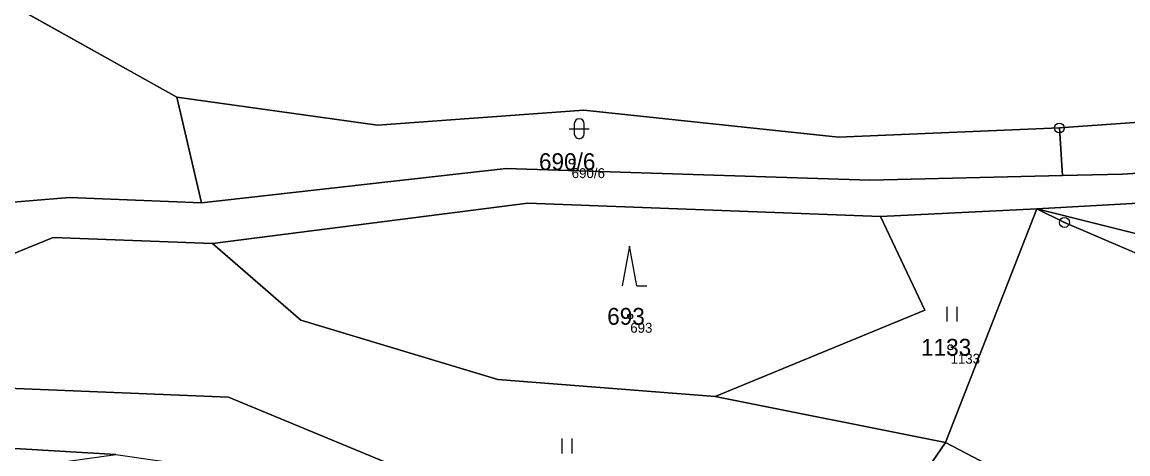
# Model space of a CAD drawing. Extents: x -554500 to -548272, y -1079733 to -1073730.
# Drawn here: x -553201.1 to -553089.7, y -1076736.6 to -1076693.1 of the extents above; entities that cross this region are included whole.
import ezdxf

# ---------------------------------------------------------------- set-up
doc = ezdxf.new("R2010")
doc.units = 0
for name, color, linetype in [('Definiční body', 7, 'Continuous'), ('Hranice parcel', 7, 'Continuous'), ('Parcelní čísla', 7, 'Continuous'), ('Polygon parcely', 7, 'Continuous'), ('Značky bodu BP', 7, 'Continuous'), ('Značky kultur', 7, 'Continuous')]:
    doc.layers.add(name, color=color, linetype=linetype)

msp = doc.modelspace()

# ---------------------------------------------------------------- linework, layer by layer
at = {"layer": 'Definiční body'}
for centre in [(-553145.73, -1076707.13994), (-553139.83, -1076722.73994), (-553107.55, -1076725.85994)]:
    msp.add_circle(centre, 0.25, dxfattribs=at)
at = {"layer": 'Hranice parcel'}
for p, q in [((-553185.54, -1076700.62), (-553217.33, -1076682.85)), ((-553183.05, -1076711.3), (-553185.54, -1076700.62)), ((-553096.58, -1076703.74), (-553096.28, -1076708.55)), ((-553098.85, -1076711.9), (-553114.62, -1076712.68)), ((-553098.85, -1076711.9), (-553108.07, -1076735.46)), ((-553108.07, -1076735.46), (-553131.27, -1076730.84))]:
    msp.add_line(p, q, dxfattribs=at)
for points in [[(-553098.85, -1076711.9), (-552980.39, -1076705.28), (-552939.43, -1076698.63), (-552921.85, -1076693.28), (-552862.63, -1076685.38), (-552777.87, -1076661.95), (-552759.32, -1076653.97), (-552709.11, -1076612.75)], [(-553040.22, -1076662.97), (-553036.57, -1076699.47), (-553096.58, -1076703.74)], [(-553096.28, -1076708.55), (-553090.21, -1076708.4), (-553016.61, -1076703.6), (-552983.69, -1076702.31), (-552965.52, -1076700.06), (-552940.21, -1076695.7), (-552920.53, -1076689.68)], [(-553185.54, -1076700.62), (-553165.31, -1076703.44), (-553144.52, -1076701.93), (-553118.83, -1076704.66), (-553096.58, -1076703.74)], [(-553183.05, -1076711.3), (-553152.34, -1076707.84), (-553115.69, -1076709.01), (-553096.28, -1076708.55)], [(-552942.15, -1076708.95), (-552975.92, -1076713.65), (-552999.87, -1076711.28), (-553084.6, -1076715.45), (-553098.85, -1076711.9)], [(-553230.16, -1076713.55), (-553196.34, -1076710.75), (-553183.05, -1076711.3)], [(-553114.62, -1076712.68), (-553150.14, -1076711.34), (-553181.93, -1076715.39)], [(-553131.27, -1076730.84), (-553110.15, -1076722.11), (-553114.62, -1076712.68)], [(-553098.85, -1076711.9), (-553096.07, -1076713.27), (-553012.42, -1076749.19), (-552945.41, -1076753.61)], [(-553181.93, -1076715.39), (-553198, -1076714.8), (-553232.31, -1076728.79)], [(-553181.93, -1076715.39), (-553173.02, -1076723.12), (-553153.18, -1076729.11), (-553131.27, -1076730.84)], [(-553091.12, -1076778.22), (-553119.71, -1076763.47), (-553143.59, -1076748.76), (-553160.35, -1076739.17), (-553180.32, -1076730.88), (-553232.31, -1076728.79)], [(-553191.68, -1076736.66), (-553222.8, -1076734.83), (-553250.13, -1076734.54)], [(-553108.07, -1076735.46), (-553121.9, -1076755.7), (-553091.12, -1076778.22)], [(-553108.07, -1076735.46), (-553058.34, -1076761.55), (-553042.36, -1076760.43)]]:
    msp.add_lwpolyline(points, dxfattribs=at)
at = {"layer": 'Polygon parcely'}
for points in [[(-552883.03, -1076530.17), (-552893.61, -1076543.86), (-552911.35, -1076561.18), (-552940.69, -1076584.39), (-552992.07, -1076615.06), (-553008.87, -1076623.57), (-553058.19, -1076636.88), (-553040.22, -1076662.97), (-553036.57, -1076699.47), (-553096.58, -1076703.74), (-553096.28, -1076708.55), (-553090.21, -1076708.4), (-553016.61, -1076703.6), (-552983.69, -1076702.31), (-552965.52, -1076700.06), (-552940.21, -1076695.7), (-552920.53, -1076689.68), (-552816.19, -1076645.7)], [(-553016.61, -1076703.6), (-553090.21, -1076708.4), (-553096.28, -1076708.55), (-553115.69, -1076709.01), (-553152.34, -1076707.84), (-553183.05, -1076711.3), (-553196.34, -1076710.75), (-553230.16, -1076713.55), (-553237.35, -1076714.14), (-553233.45, -1076716.22), (-553207.22, -1076714.58), (-553240.89, -1076728.79), (-553232.31, -1076728.79), (-553198, -1076714.8), (-553181.93, -1076715.39), (-553150.14, -1076711.34), (-553114.62, -1076712.68), (-553098.85, -1076711.9), (-552980.39, -1076705.28)], [(-552881.45, -1076791.87), (-552910.41, -1076794.05), (-552933.34, -1076795.77), (-552951.53, -1076797.14), (-553023.39, -1076800.01), (-553046.46, -1076797.42), (-553056.33, -1076796.31), (-553072.69, -1076790.18), (-553091.12, -1076778.22), (-553119.71, -1076763.47), (-553143.59, -1076748.76), (-553160.35, -1076739.17), (-553180.32, -1076730.88), (-553232.31, -1076728.79), (-553240.89, -1076728.79), (-553252.25, -1076728.8), (-553264.63, -1076725.36), (-553265.24, -1076727.16), (-553281.96, -1076725.1), (-553286.43, -1076723.11), (-553324.92, -1076706.74)], [(-553295.92, -1076725.99), (-553250.13, -1076734.54), (-553222.8, -1076734.83), (-553191.68, -1076736.66), (-553183.51, -1076737.85), (-553171.5, -1076741.23), (-553130.21, -1076764.82), (-553091.28, -1076787.95), (-553068.2, -1076799.98), (-553063.96, -1076801.36), (-553045.17, -1076807.78), (-553029.11, -1076807.94), (-553027.64, -1076807.87), (-552993.85, -1076806.25), (-552969.71, -1076805.01), (-552957.63, -1076804.39), (-552947.93, -1076803.82), (-552920.81, -1076802.22), (-552896.7, -1076800.6), (-552872.59, -1076798.97), (-552853.76, -1076797.7), (-552839.22, -1076797.7), (-552831.61, -1076797.51)]]:
    msp.add_lwpolyline(points, dxfattribs=at)
for points in [[(-552761.39, -1076662.66), (-552741.74, -1076649.53), (-552724.82, -1076631.37), (-552709.11, -1076612.75), (-552759.32, -1076653.97), (-552777.87, -1076661.95), (-552862.63, -1076685.38), (-552921.85, -1076693.28), (-552939.43, -1076698.63), (-552980.39, -1076705.28), (-553098.85, -1076711.9), (-553084.6, -1076715.45), (-552999.87, -1076711.28), (-552975.92, -1076713.65), (-552942.15, -1076708.95), (-552937.05, -1076708.24), (-552937.81, -1076716.99), (-552852.69, -1076714.91), (-552829.92, -1076702.39), (-552825.68, -1076694.53)], [(-553144.52, -1076701.93), (-553118.83, -1076704.66), (-553096.58, -1076703.74), (-553036.57, -1076699.47), (-553040.22, -1076662.97), (-553149.04, -1076680.48), (-553164.8, -1076674.91), (-553217.33, -1076682.85), (-553185.54, -1076700.62), (-553165.31, -1076703.44)], [(-553217.33, -1076682.85), (-553214.52, -1076674.83), (-553239.34, -1076680.59), (-553254.35, -1076687.61), (-553262.59, -1076693.65), (-553260.52, -1076694.73), (-553258.95, -1076693.29), (-553256.15, -1076696.34), (-553253.66, -1076693.99), (-553247.75, -1076700.26), (-553248.88, -1076701.33), (-553230.16, -1076713.55), (-553196.34, -1076710.75), (-553183.05, -1076711.3), (-553185.54, -1076700.62)], [(-553115.69, -1076709.01), (-553096.28, -1076708.55), (-553096.58, -1076703.74), (-553118.83, -1076704.66), (-553144.52, -1076701.93), (-553165.31, -1076703.44), (-553185.54, -1076700.62), (-553183.05, -1076711.3), (-553152.34, -1076707.84)], [(-553098.85, -1076711.9), (-553096.07, -1076713.27), (-553012.42, -1076749.19), (-552945.41, -1076753.61), (-552942.15, -1076708.95), (-552975.92, -1076713.65), (-552999.87, -1076711.28), (-553084.6, -1076715.45)], [(-553153.18, -1076729.11), (-553131.27, -1076730.84), (-553110.15, -1076722.11), (-553114.62, -1076712.68), (-553150.14, -1076711.34), (-553181.93, -1076715.39), (-553173.02, -1076723.12)], [(-553098.85, -1076711.9), (-553114.62, -1076712.68), (-553110.15, -1076722.11), (-553131.27, -1076730.84), (-553108.07, -1076735.46)], [(-553058.34, -1076761.55), (-553042.36, -1076760.43), (-552945.46, -1076754.34), (-552945.41, -1076753.61), (-553012.42, -1076749.19), (-553096.07, -1076713.27), (-553098.85, -1076711.9), (-553108.07, -1076735.46)], [(-553181.93, -1076715.39), (-553198, -1076714.8), (-553232.31, -1076728.79), (-553180.32, -1076730.88), (-553160.35, -1076739.17), (-553143.59, -1076748.76), (-553119.71, -1076763.47), (-553091.12, -1076778.22), (-553121.9, -1076755.7), (-553108.07, -1076735.46), (-553131.27, -1076730.84), (-553153.18, -1076729.11), (-553173.02, -1076723.12)], [(-553207.11, -1076738.82), (-553191.68, -1076736.66), (-553222.8, -1076734.83), (-553250.13, -1076734.54), (-553232.77, -1076739.45), (-553203.09, -1076746.12), (-553209.5, -1076743.16)], [(-553072.69, -1076790.18), (-553056.33, -1076796.31), (-553046.46, -1076797.42), (-553042.36, -1076760.43), (-553058.34, -1076761.55), (-553108.07, -1076735.46), (-553121.9, -1076755.7), (-553091.12, -1076778.22)]]:
    msp.add_lwpolyline(points, close=True, dxfattribs=at)
at = {"layer": 'Značky bodu BP'}
for centre, radius in [((-553096.58, -1076703.73988), 0.5), ((-553096.58, -1076703.73988), 0.0303), ((-553096.07, -1076713.26988), 0.5), ((-553096.07, -1076713.26988), 0.0303)]:
    msp.add_circle(centre, radius, dxfattribs=at)
at = {"layer": 'Značky kultur'}
for p, q in [((-553145.971, -1076703.821), (-553143.969, -1076703.821)), ((-553145.471, -1076703.321), (-553145.471, -1076704.322)), ((-553144.469, -1076704.322), (-553144.469, -1076703.321)), ((-553139.91, -1076715.67), (-553140.66, -1076719.67)), ((-553139.16, -1076719.67), (-553139.91, -1076715.67)), ((-553139.16, -1076719.67), (-553138.164, -1076719.67)), ((-553107.881, -1076723.27), (-553107.881, -1076721.77)), ((-553106.88, -1076723.27), (-553106.88, -1076721.77)), ((-553146.701, -1076736.57), (-553146.701, -1076735.07)), ((-553145.7, -1076736.57), (-553145.7, -1076735.07))]:
    msp.add_line(p, q, dxfattribs=at)
for centre, start, end in [((-553144.97, -1076703.3209), 0, 180), ((-553144.97, -1076704.3209), 180, 359.9878861)]:
    msp.add_arc(centre, 0.5, start, end, dxfattribs=at)

# ---------------------------------------------------------------- texts
at = {"layer": 'Definiční body'}
for s, p in [('690/6', (-553145.73, -1076708.796)), ('693', (-553139.83, -1076724.396)), ('1133', (-553107.55, -1076727.516))]:
    msp.add_text(s, height=0.999996, dxfattribs=at).set_placement(p)
at = {"layer": 'Parcelní čísla'}
for s, p in [('690/6', (-553149.028, -1076707.99)), ('693', (-553142.155, -1076723.59)), ('1133', (-553110.524, -1076726.71))]:
    msp.add_text(s, height=1.699998, dxfattribs=at).set_placement(p)

doc.saveas('drawing.dxf')
